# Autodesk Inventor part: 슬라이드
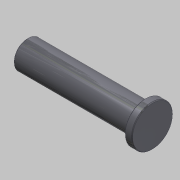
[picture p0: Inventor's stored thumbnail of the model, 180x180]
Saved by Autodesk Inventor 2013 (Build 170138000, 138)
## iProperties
Created: 2015-10
Part Number: 슬라이드
Document SubType Name: Modeling
Designer: mdu
Density: 7.86 g/cm^3
Material: 강철, 연강
Mass: 1589.24 g
Surface Area: 264.883 cm^2
Volume: 202.193 cm^3
Author: mdu
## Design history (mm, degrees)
sketch "스케치1"
  geometry: L1 (-75, 162)-(-75, 58) reference; L2 (-148, 110)-(22, 110); L3 (-148, 110)-(-148, 129); L4 (-148, 129)-(12, 129); L5 (12, 129)-(12, 138); L6 (12, 138)-(22, 138); L7 (22, 138)-(22, 110); 2 further points
  constraints: 12 end point, 3 parallel, 3 perpendicular, 1 midpoint, 1 point on line
  dimensions: "d0" = 56 diameter of L6 L2; "d1" = 38 diameter of L4 L2; "d2" = 10 distance of L5.end L6.end; "d3" = 170 distance of L2.start L2.end; "d4" = 73 distance between parallel lines of L3 L1
revolve "회전1" sketch "스케치1" stored, may be unused: angle "d5" = 90 deg
hole "구멍1" diameter "d11" = 13.376; stored, may be unused: countersink angle "d15" = 90 deg, drill point angle "d17" = 118 deg; dims "d9" = 10, "d10" = 10, "d12" = 22, "d13" = 4, "d14" = 2, "d16" = 25
chamfer "모따기1" distance "d6" = 1; stored, may be unused: second distance "d7" = 2, angle "d8" = 45 deg
node "솔리드1"
node "참조1"
